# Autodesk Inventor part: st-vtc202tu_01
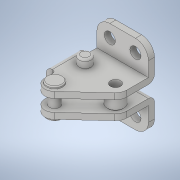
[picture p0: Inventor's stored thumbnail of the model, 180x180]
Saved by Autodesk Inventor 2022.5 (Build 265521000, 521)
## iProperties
Created: 2021-08
Part Number: st-vtc202tu_01
Material: 一般
Document SubType Name: Modeling
Designer: ImaoCorp
Density: 1 g/cm^3
Appearance: 既定
Author: ImaoCorp
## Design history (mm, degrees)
feature "st-vtc202tu_01"
node "ソリッド1"
